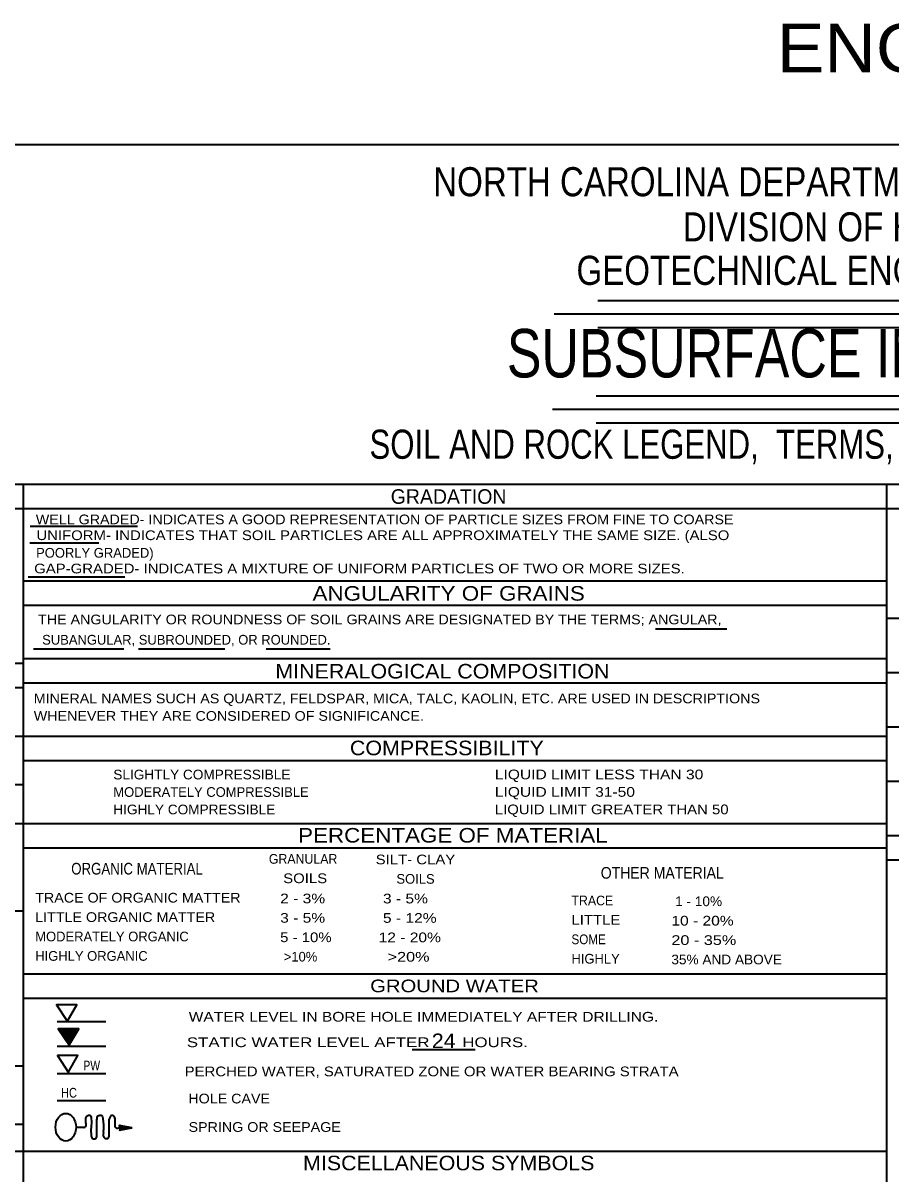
# Model space of a CAD drawing. Extents: x 2137492.6 to 2137529.1, y 2137475.8 to 2137563.
# Drawn here: x 2137501.87 to 2137510.82, y 2137551.11 to 2137562.97 of the extents above; entities that cross this region are included whole.
import ezdxf
from ezdxf.enums import TextEntityAlignment as Align

# ---------------------------------------------------------------- set-up
doc = ezdxf.new("R2010")
doc.units = 0
doc.header["$LTSCALE"] = 0.04
doc.layers.add('1', color=7, linetype='Continuous', lineweight=35)

msp = doc.modelspace()

# ---------------------------------------------------------------- linework, layer by layer
at = {"layer": '1'}
for p, q in [((2137493.171, 2137561.718), (2137528.371, 2137561.718)), ((2137507.793, 2137560.112), (2137513.652, 2137560.112)), ((2137507.345, 2137559.974), (2137514.203, 2137559.974)), ((2137507.793, 2137559.832), (2137513.652, 2137559.832)), ((2137507.776, 2137559.129), (2137513.635, 2137559.129)), ((2137507.328, 2137558.991), (2137514.186, 2137558.991)), ((2137507.776, 2137558.849), (2137513.635, 2137558.849)), ((2137493.171, 2137558.218), (2137528.371, 2137558.218)), ((2137501.871, 2137558.218), (2137501.871, 2137539.727)), ((2137510.771, 2137558.218), (2137510.771, 2137539.727)), ((2137493.171, 2137557.968), (2137528.371, 2137557.968)), ((2137501.941, 2137557.784), (2137503.049, 2137557.784)), ((2137501.937, 2137557.614), (2137502.649, 2137557.614)), ((2137501.921, 2137557.264), (2137502.919, 2137557.264)), ((2137510.771, 2137557.218), (2137501.871, 2137557.218)), ((2137510.771, 2137556.968), (2137501.871, 2137556.968)), ((2137519.912, 2137556.833), (2137510.771, 2137556.833)), ((2137508.388, 2137556.728), (2137509.125, 2137556.728)), ((2137501.976, 2137556.521), (2137502.906, 2137556.521)), ((2137503.058, 2137556.522), (2137503.947, 2137556.522)), ((2137504.375, 2137556.521), (2137505.035, 2137556.521)), ((2137510.771, 2137556.418), (2137501.871, 2137556.418)), ((2137493.171, 2137556.373), (2137501.871, 2137556.373)), ((2137510.771, 2137556.168), (2137501.871, 2137556.168)), ((2137519.912, 2137556.273), (2137510.771, 2137556.273)), ((2137493.171, 2137556.123), (2137501.871, 2137556.123)), ((2137519.912, 2137555.713), (2137510.771, 2137555.713)), ((2137493.171, 2137555.623), (2137501.871, 2137555.623)), ((2137510.771, 2137555.618), (2137501.871, 2137555.618)), ((2137510.771, 2137555.368), (2137501.871, 2137555.368)), ((2137493.171, 2137555.123), (2137501.871, 2137555.123)), ((2137519.912, 2137555.153), (2137510.771, 2137555.153)), ((2137493.171, 2137554.723), (2137501.871, 2137554.723)), ((2137510.771, 2137554.718), (2137501.871, 2137554.718)), ((2137519.912, 2137554.593), (2137510.771, 2137554.593)), ((2137510.771, 2137554.468), (2137501.871, 2137554.468)), ((2137519.912, 2137554.343), (2137510.771, 2137554.343)), ((2137493.171, 2137553.823), (2137501.871, 2137553.823)), ((2137510.771, 2137553.168), (2137501.871, 2137553.168)), ((2137510.171, 2137553.168), (2137501.871, 2137553.168)), ((2137510.771, 2137552.918), (2137501.871, 2137552.918)), ((2137502.221, 2137552.682), (2137502.721, 2137552.682)), ((2137502.221, 2137552.427), (2137502.721, 2137552.427)), ((2137505.881, 2137552.392), (2137506.53, 2137552.392)), ((2137493.171, 2137552.223), (2137501.871, 2137552.223)), ((2137502.221, 2137552.146), (2137502.721, 2137552.146)), ((2137502.221, 2137551.866), (2137502.721, 2137551.866)), ((2137493.171, 2137551.623), (2137501.871, 2137551.623)), ((2137502.872, 2137551.582), (2137502.93, 2137551.593)), ((2137502.872, 2137551.582), (2137502.93, 2137551.593)), ((2137502.872, 2137551.581), (2137502.93, 2137551.592)), ((2137502.872, 2137551.58), (2137502.93, 2137551.591)), ((2137502.872, 2137551.579), (2137502.93, 2137551.59)), ((2137502.872, 2137551.578), (2137502.93, 2137551.589)), ((2137502.872, 2137551.578), (2137502.93, 2137551.589)), ((2137502.873, 2137551.577), (2137502.931, 2137551.588)), ((2137502.873, 2137551.576), (2137502.931, 2137551.587)), ((2137502.873, 2137551.575), (2137502.931, 2137551.586)), ((2137502.873, 2137551.574), (2137502.931, 2137551.585)), ((2137502.873, 2137551.573), (2137502.931, 2137551.584)), ((2137502.873, 2137551.572), (2137502.931, 2137551.583)), ((2137502.873, 2137551.572), (2137502.931, 2137551.583)), ((2137502.874, 2137551.591), (2137502.933, 2137551.581)), ((2137502.874, 2137551.591), (2137502.933, 2137551.581)), ((2137502.874, 2137551.59), (2137502.933, 2137551.58)), ((2137502.874, 2137551.571), (2137502.932, 2137551.582)), ((2137502.874, 2137551.57), (2137502.932, 2137551.581)), ((2137502.874, 2137551.569), (2137502.932, 2137551.58)), ((2137502.874, 2137551.568), (2137502.932, 2137551.579)), ((2137502.874, 2137551.568), (2137502.932, 2137551.579)), ((2137502.874, 2137551.567), (2137502.932, 2137551.578)), ((2137502.875, 2137551.598), (2137502.934, 2137551.588)), ((2137502.875, 2137551.597), (2137502.934, 2137551.587)), ((2137502.875, 2137551.596), (2137502.934, 2137551.586)), ((2137502.875, 2137551.595), (2137502.934, 2137551.585)), ((2137502.875, 2137551.594), (2137502.934, 2137551.584)), ((2137502.875, 2137551.593), (2137502.934, 2137551.583)), ((2137502.875, 2137551.566), (2137502.933, 2137551.577)), ((2137502.876, 2137551.603), (2137502.935, 2137551.593)), ((2137502.876, 2137551.601), (2137502.935, 2137551.591)), ((2137502.876, 2137551.6), (2137502.935, 2137551.59)), ((2137502.876, 2137551.599), (2137502.935, 2137551.589)), ((2137502.877, 2137551.604), (2137502.936, 2137551.594)), ((2137502.878, 2137551.606), (2137502.986, 2137551.586)), ((2137510.771, 2137551.34), (2137493.171, 2137551.34))]:
    msp.add_line(p, q, dxfattribs=at)
for points in [[(2137502.322, 2137552.68), (2137502.422, 2137552.853), (2137502.212, 2137552.853), (2137502.327, 2137552.68)], [(2137502.342, 2137552.433), (2137502.442, 2137552.606), (2137502.232, 2137552.606), (2137502.347, 2137552.433)], [(2137502.253, 2137552.594), (2137502.426, 2137552.594), (2137502.344, 2137552.455), (2137502.255, 2137552.589), (2137502.42, 2137552.589), (2137502.344, 2137552.464), (2137502.263, 2137552.584), (2137502.411, 2137552.584), (2137502.344, 2137552.475), (2137502.274, 2137552.578), (2137502.401, 2137552.578), (2137502.343, 2137552.486), (2137502.283, 2137552.572), (2137502.391, 2137552.571), (2137502.342, 2137552.496), (2137502.293, 2137552.566), (2137502.383, 2137552.566), (2137502.342, 2137552.505), (2137502.303, 2137552.561), (2137502.374, 2137552.561), (2137502.342, 2137552.516), (2137502.313, 2137552.557), (2137502.366, 2137552.557), (2137502.343, 2137552.525), (2137502.324, 2137552.552), (2137502.356, 2137552.552), (2137502.342, 2137552.53), (2137502.333, 2137552.547), (2137502.349, 2137552.548), (2137502.342, 2137552.54)], [(2137502.332, 2137552.157), (2137502.432, 2137552.33), (2137502.222, 2137552.33), (2137502.337, 2137552.157)], [(2137502.993, 2137551.586), (2137502.861, 2137551.611), (2137502.875, 2137551.587), (2137502.863, 2137551.561), (2137502.99, 2137551.585)], [(2137502.863, 2137551.61), (2137502.877, 2137551.586), (2137502.877, 2137551.607), (2137502.864, 2137551.61), (2137502.876, 2137551.59), (2137502.876, 2137551.606), (2137502.866, 2137551.608), (2137502.875, 2137551.593), (2137502.875, 2137551.605), (2137502.868, 2137551.606), (2137502.874, 2137551.598), (2137502.874, 2137551.596), (2137502.874, 2137551.603), (2137502.87, 2137551.604), (2137502.874, 2137551.604), (2137502.872, 2137551.601), (2137502.878, 2137551.585), (2137502.876, 2137551.585), (2137502.875, 2137551.584), (2137502.865, 2137551.562), (2137502.875, 2137551.564), (2137502.878, 2137551.585), (2137502.876, 2137551.583), (2137502.867, 2137551.563), (2137502.874, 2137551.565), (2137502.876, 2137551.582), (2137502.869, 2137551.564), (2137502.873, 2137551.566), (2137502.874, 2137551.576), (2137502.871, 2137551.565), (2137502.877, 2137551.565), (2137502.988, 2137551.586)], [(2137502.936, 2137551.593), (2137502.982, 2137551.586), (2137502.934, 2137551.577), (2137502.936, 2137551.592), (2137502.976, 2137551.586), (2137502.935, 2137551.579), (2137502.937, 2137551.59), (2137502.97, 2137551.585), (2137502.965, 2137551.587), (2137502.936, 2137551.591), (2137502.936, 2137551.58), (2137502.967, 2137551.585), (2137502.937, 2137551.589), (2137502.936, 2137551.582), (2137502.962, 2137551.585), (2137502.937, 2137551.588), (2137502.938, 2137551.583), (2137502.957, 2137551.586), (2137502.937, 2137551.587), (2137502.937, 2137551.583), (2137502.95, 2137551.587), (2137502.938, 2137551.585), (2137502.937, 2137551.581), (2137502.951, 2137551.583), (2137502.938, 2137551.594), (2137502.957, 2137551.59), (2137502.936, 2137551.594), (2137502.877, 2137551.587), (2137502.883, 2137551.585), (2137502.885, 2137551.586), (2137502.885, 2137551.587), (2137502.89, 2137551.587), (2137502.89, 2137551.588), (2137502.88, 2137551.602), (2137502.899, 2137551.598), (2137502.898, 2137551.601), (2137502.878, 2137551.605)], [(2137502.878, 2137551.588), (2137502.887, 2137551.586), (2137502.877, 2137551.584), (2137502.901, 2137551.589), (2137502.878, 2137551.591), (2137502.898, 2137551.587), (2137502.893, 2137551.591), (2137502.877, 2137551.603), (2137502.922, 2137551.594), (2137502.935, 2137551.592), (2137502.934, 2137551.576), (2137502.932, 2137551.584)]]:
    msp.add_lwpolyline(points, dxfattribs=at)
msp.add_lwpolyline([(2137502.242, 2137552.6), (2137502.435, 2137552.6), (2137502.344, 2137552.446)], close=True, dxfattribs=at)
msp.add_ellipse((2137502.30865, 2137551.59195), major_axis=(0, -0.1425), ratio=0.743839, dxfattribs=at)
msp.add_spline([(2137502.415, 2137551.592), (2137502.491, 2137551.591), (2137502.507, 2137551.591), (2137502.517, 2137551.639), (2137502.517, 2137551.684), (2137502.522, 2137551.698), (2137502.529, 2137551.71), (2137502.557, 2137551.715), (2137502.572, 2137551.681), (2137502.569, 2137551.586), (2137502.569, 2137551.529), (2137502.572, 2137551.5), (2137502.586, 2137551.477), (2137502.607, 2137551.472), (2137502.615, 2137551.474), (2137502.629, 2137551.505), (2137502.629, 2137551.538), (2137502.629, 2137551.636), (2137502.629, 2137551.667), (2137502.634, 2137551.691), (2137502.641, 2137551.71), (2137502.653, 2137551.712), (2137502.667, 2137551.717), (2137502.679, 2137551.712), (2137502.686, 2137551.698), (2137502.696, 2137551.643), (2137502.696, 2137551.546), (2137502.696, 2137551.519), (2137502.7, 2137551.488), (2137502.715, 2137551.477), (2137502.734, 2137551.474), (2137502.748, 2137551.481), (2137502.755, 2137551.5), (2137502.755, 2137551.529), (2137502.755, 2137551.641), (2137502.755, 2137551.662), (2137502.762, 2137551.686), (2137502.769, 2137551.698), (2137502.777, 2137551.71), (2137502.784, 2137551.717), (2137502.793, 2137551.715), (2137502.805, 2137551.705), (2137502.812, 2137551.689), (2137502.815, 2137551.67), (2137502.815, 2137551.627), (2137502.815, 2137551.603), (2137502.829, 2137551.584), (2137502.86, 2137551.586), (2137502.917, 2137551.586), (2137502.993, 2137551.586)], degree=3, dxfattribs=at)

# ---------------------------------------------------------------- texts
for s, height, width, p in [('ENGLISH', 0.5, 1.1, (2137511.253, 2137562.463)), ('NORTH CAROLINA DEPARTMENT OF TRANSPORTATION', 0.3, 0.85, (2137510.748, 2137561.185)), ('DIVISION OF HIGHWAYS', 0.3, 0.85, (2137510.679, 2137560.72)), ('GEOTECHNICAL ENGINEERING UNIT', 0.3, 0.85, (2137510.605, 2137560.272)), ('SUBSURFACE INVESTIGATION', 0.5, 0.8, (2137510.824, 2137559.318)), ('SOIL AND ROCK LEGEND,  TERMS,  SYMBOLS,  AND ABBREVIATIONS', 0.3, 0.8, (2137510.817, 2137558.48)), ('THE ANGULARITY OR ROUNDNESS OF SOIL GRAINS ARE DESIGNATED BY THE TERMS; ANGULAR,', 0.1, 1.1, (2137505.546, 2137556.774)), ('GRANULAR', 0.1, 0.95, (2137504.7555, 2137554.307)), ('SILT- CLAY', 0.1, 1.15, (2137505.914, 2137554.301)), ('ORGANIC MATERIAL', 0.12, 0.85, (2137503.0435, 2137554.196)), ('OTHER MATERIAL', 0.12, 0.9, (2137508.458, 2137554.153)), (' SOILS', 0.1, 1.15, (2137504.7555, 2137554.107)), ('GROUND WATER', 0.13, 1.2, (2137506.316, 2137552.983)), ('WATER LEVEL IN BORE HOLE IMMEDIATELY AFTER DRILLING.', 0.1, 1.2, (2137505.997, 2137552.68)), ('STATIC WATER LEVEL AFTER       HOURS.', 0.1, 1.3, (2137505.315, 2137552.417)), ('PW', 0.1, 0.8, (2137502.5765, 2137552.177)), ('PERCHED WATER, SATURATED ZONE OR WATER BEARING STRATA', 0.1, 1.15, (2137506.0805, 2137552.117)), ('HC', 0.1, 0.85, (2137502.342, 2137551.897)), ('HOLE CAVE', 0.1, 1.1, (2137503.9935, 2137551.837)), ('SPRING OR SEEPAGE', 0.1, 1.1, (2137504.3595, 2137551.544))]:
    msp.add_text(s, height=height, dxfattribs=dict(at, width=width)).set_placement(p, align=Align.CENTER)
for s, height, p in [('GRADATION', 0.15, (2137505.659, 2137558.016)), ('POORLY GRADED)', 0.1, (2137502.003, 2137557.461)), ('MODERATELY COMPRESSIBLE', 0.1, (2137502.799, 2137554.996)), ('MODERATELY ORGANIC', 0.1, (2137501.994, 2137553.507)), ('HIGHLY ORGANIC', 0.1, (2137501.994, 2137553.307)), (' >10%', 0.1, (2137504.519, 2137553.299)), ('HIGHLY', 0.1, (2137507.522, 2137553.278))]:
    msp.add_text(s, height=height, dxfattribs=at).set_placement(p)
for s, height, width, p in [('WELL GRADED- INDICATES A GOOD REPRESENTATION OF PARTICLE SIZES FROM FINE TO COARSE', 0.1, 1.1, (2137502, 2137557.805)), ('UNIFORM- INDICATES THAT SOIL PARTICLES ARE ALL APPROXIMATELY THE SAME SIZE. (ALSO', 0.1, 1.15, (2137502.006, 2137557.642)), ('GAP-GRADED- INDICATES A MIXTURE OF UNIFORM PARTICLES OF TWO OR MORE SIZES.', 0.1, 1.15, (2137501.983, 2137557.299)), ('ANGULARITY OF GRAINS', 0.15, 1.15, (2137504.853, 2137557.018)), ('MINERALOGICAL COMPOSITION', 0.15, 1.1, (2137504.469, 2137556.216)), ('MINERAL NAMES SUCH AS QUARTZ, FELDSPAR, MICA, TALC, KAOLIN, ETC. ARE USED IN DESCRIPTIONS ', 0.1, 1.1, (2137501.979, 2137555.96)), ('WHENEVER THEY ARE CONSIDERED OF SIGNIFICANCE.', 0.1, 1.1, (2137501.979, 2137555.78)), ('COMPRESSIBILITY', 0.15, 1.1, (2137505.238, 2137555.425)), ('SLIGHTLY COMPRESSIBLE', 0.1, 1.05, (2137502.799, 2137555.176)), ('LIQUID LIMIT LESS THAN 30', 0.1, 1.2, (2137506.732, 2137555.177)), ('LIQUID LIMIT 31-50', 0.1, 1.2, (2137506.732, 2137554.997)), ('HIGHLY COMPRESSIBLE', 0.1, 1.05, (2137502.799, 2137554.816)), ('LIQUID LIMIT GREATER THAN 50', 0.1, 1.15, (2137506.732, 2137554.817)), ('PERCENTAGE OF MATERIAL', 0.15, 1.15, (2137504.704, 2137554.525)), ('TRACE OF ORGANIC MATTER', 0.1, 1.1, (2137501.994, 2137553.907)), ('2 - 3%', 0.1, 1.2, (2137504.519, 2137553.899)), (' 3 - 5%', 0.1, 1.2, (2137505.534, 2137553.898)), ('TRACE', 0.1, 0.95, (2137507.522, 2137553.878)), (' 1 - 10%', 0.1, 1.05, (2137508.552, 2137553.87)), ('LITTLE ORGANIC MATTER', 0.1, 1.1, (2137501.994, 2137553.707)), ('3 - 5%', 0.1, 1.2, (2137504.519, 2137553.699)), (' 5 - 12%', 0.1, 1.2, (2137505.534, 2137553.698)), ('LITTLE', 0.1, 1.15, (2137507.522, 2137553.678)), ('10 - 20%', 0.1, 1.2, (2137508.552, 2137553.67)), ('5 - 10%', 0.1, 1.15, (2137504.519, 2137553.499)), ('12 - 20%', 0.1, 1.2, (2137505.534, 2137553.498)), ('SOME', 0.1, 0.9, (2137507.522, 2137553.478)), ('20 - 35%', 0.1, 1.25, (2137508.552, 2137553.47)), ('  >20%', 0.1, 1.25, (2137505.534, 2137553.298)), ('35% AND ABOVE', 0.1, 1.05, (2137508.552, 2137553.27)), ('24', 0.15, 1.1, (2137506.082, 2137552.407)), ('MISCELLANEOUS SYMBOLS', 0.15, 1.1, (2137504.755, 2137551.148))]:
    msp.add_text(s, height=height, dxfattribs=dict(at, width=width)).set_placement(p)
for s, p in [('SUBANGULAR, SUBROUNDED, OR ROUNDED.', (2137503.5515, 2137556.565)), ('SOILS', (2137505.9145, 2137554.101))]:
    msp.add_text(s, height=0.1, dxfattribs=at).set_placement(p, align=Align.CENTER)

doc.saveas('drawing.dxf')
